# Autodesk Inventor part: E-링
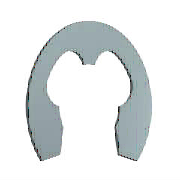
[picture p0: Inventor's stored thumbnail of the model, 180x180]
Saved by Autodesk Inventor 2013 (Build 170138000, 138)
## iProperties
IsCustomPart: 1
Created: 2012-02
Part Number: E-링
Material: 강철, 연강
Description: 일반용 테이퍼 및 줄어든 횡단면 리테이닝 링 - E-링 외부 시리즈 3CM1 리테이닝 링
Document SubType Name: Modeling
Standard: ANSI B27.7
Designer: mduedu
Standard Revision: 1999
Standards Organization: ANSI
Language: ko-KR
Size Designation: 6
Categories: <MemberInstance><Categories><Category DisplayName="샤프트 부품" InternalName="7f7aeb1f-a693-4053-b835-cee3144e0d98" Mnemonic="SHFT"><Category DisplayName="써클립" Inter
Density: 1 g/cm^3
Author: mduedu
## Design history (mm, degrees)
sketch "스케치1"
  geometry: L1 (-0.485, 0.024)-(0, 0.024) reference; L2 (-3.206, 0)-(3.486, 0) reference; L3 (-2.223, -3.946)-(2.223, -3.946); L4 (0, 1.949)-(0, -3.479) reference; L5 (-2.91, -2.006)-(-2.435, -2.006); L6 (-0.485, -0.066)-(-0.485, 0.405); L7 (0, 2.574)-(2.53, 2.574); L8 (-2.223, -3.946)-(-3.022, -6.291); L9 (0, -0.551)-(-1.278, -0.551); L10 (2.223, -3.946)-(3.022, -6.291); L11 (2.91, -2.006)-(2.435, -2.006); L12 (0.485, -0.066)-(0.485, 0.405); C1 r 3 at (0, -2.976); A1 r 2.425 centre (0, -2.976) between (-2.297, -2.199) and (-2.223, -3.946); A2 r 0.485 centre (0, -0.066) between (-0.485, -0.066) and (0.485, -0.066); A3 r 5.55 centre (0, -2.976) between (4.27, -6.521) and (-4.27, -6.521); A4 r 3.88 centre (0, -2.976) between (-0.97, 0.78) and (-3.424, -1.15); A5 r 0.388 centre (-0.873, 0.405) between (-0.485, 0.405) and (-0.97, 0.78); A6 r 0.582 centre (-2.91, -1.424) between (-3.424, -1.15) and (-2.91, -2.006); A7 r 0.145 centre (-2.435, -2.152) between (-2.297, -2.199) and (-2.435, -2.006); A8 r 0.727 centre (-3.711, -6.057) between (-4.27, -6.521) and (-3.022, -6.291); A9 r 0.727 centre (3.711, -6.057) between (3.022, -6.291) and (4.27, -6.521); A10 r 2.425 centre (0, -2.976) between (2.223, -3.946) and (2.297, -2.199); A11 r 0.145 centre (2.435, -2.152) between (2.435, -2.006) and (2.297, -2.199); A12 r 0.582 centre (2.91, -1.424) between (2.91, -2.006) and (3.424, -1.15); A13 r 3.88 centre (0, -2.976) between (3.424, -1.15) and (0.97, 0.78); A14 r 0.388 centre (0.873, 0.405) between (0.97, 0.78) and (0.485, 0.405); 1 further point
  constraints: 30 point on circle, 20 end point, 15 centre point, 13 symmetric about line, 12 tangent, 8 point on line, 4 parallel, 2 coincident, 2 horizontal, 1 concentric, 1 perpendicular, 1 vertical alignment, 9 other
  dimensions: "d0" = 6 diameter of C1 (= WD); "d3" = 0.97 distance from line of A1.centre L3 (= 0.2 x ND); "d4" = 0.485 radius of A2 (= 0.1 x ND); "d5" = 11.1 diameter of A3 (= SD2); "d8" = 3.88 radius of A4 (= 0.8 x ND); "d9" = 0.97 distance from line of A1.centre L5 (= 0.2 x ND); "d10" = 0.388 radius of A5 (= 0.08 x ND); "d11" = 0.582 radius of A6 (= 0.12 x ND); "d12" = 0.1455 radius of A7 (= 0.03 x ND); "d13" = 0.7275 radius of A8 (= 0.15 x ND); "d14" = 2.425 distance from line of A1.centre L9 (= 0.5 x ND); "d15" = 2.425 radius of A1 (= 0.5 x ND)
extrude "본체" new body sketch "스케치1" distance "d16" = 0.6 (= SD); taper "d17" = 0 deg
workaxis "Work Axis1"
workaxis "Work Axis2"
workplane "Work Plane1"
body "Solid1"
other parameters: "ND" = 4.85 [user parameter; used in 14 equation terms], "SD" = 0.6 [user parameter; used in 1 equation term], "WD" = 6 (= WDMIN) [user parameter; used in 1 equation term], "d1" = 7.76 (= 1.6 x ND), "d2" = 4.85 (= ND), "SD2" = 11.1 [user parameter; used in 1 equation term], "d6" = 4.85 (= ND), "d7" = 0.7275 (= 0.15 x ND), "d18" = 0, "d19" = 0, "d27" = 0, "d28" = 0, "WDMIN" = 6 [user parameter; used in 1 equation term], "SNB" = 0.7 [user parameter], "WDMAX" = 7 [user parameter], "BUBRMI" = 1.2 [user parameter]
